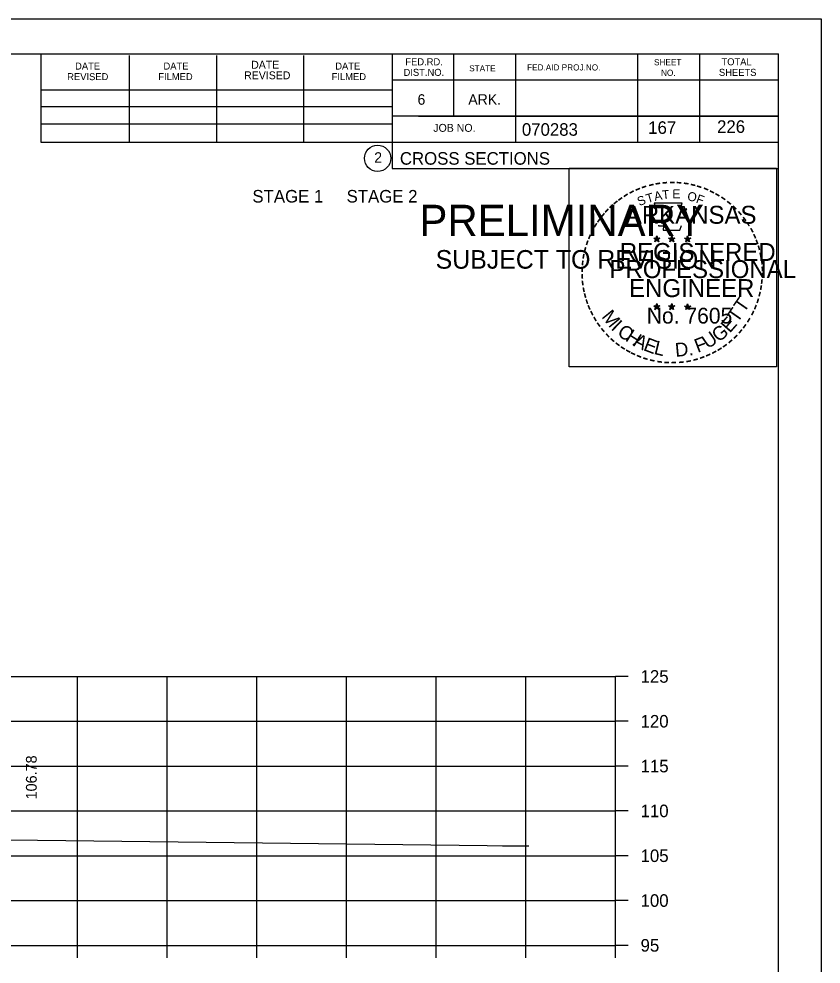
# Model space of a CAD drawing. Extents: x 1175611 to 1176402, y -433344 to -416213.
# Drawn here: x 1175854.4 to 1175943.9, y -428968.9 to -428863.4 of the extents above; entities that cross this region are included whole.
import ezdxf

# ---------------------------------------------------------------- set-up
doc = ezdxf.new("R2010")
doc.units = 0
for name, color, linetype in [('Default', 7, 'Continuous'), ('R_Axis', 7, 'Continuous'), ('R_Axis Annot', 7, 'Continuous'), ('R_Border', 7, 'Continuous'), ('R_Border Notes', 7, 'Continuous'), ('R_Border PE', 7, 'Continuous'), ('R_Border Prem', 7, 'Continuous'), ('R_Exist Surface', 7, 'Continuous'), ('R_Grid', 7, 'Continuous'), ('R_No Plot', 7, 'Continuous'), ('R_Xsect Elev', 7, 'Continuous')]:
    doc.layers.add(name, color=color, linetype=linetype)

msp = doc.modelspace()

# ---------------------------------------------------------------- linework, layer by layer
at = {"layer": 'R_Axis'}
for p, q in [((1175920.97, -428966.79), (1175920.97, -428936.79)), ((1175922.37, -428936.79), (1175920.97, -428936.79)), ((1175922.37, -428941.79), (1175920.97, -428941.79)), ((1175922.37, -428946.79), (1175920.97, -428946.79)), ((1175922.37, -428951.79), (1175920.97, -428951.79)), ((1175922.37, -428956.79), (1175920.97, -428956.79)), ((1175922.37, -428961.79), (1175920.97, -428961.79)), ((1175640.97, -428966.79), (1175920.97, -428966.79)), ((1175860.97, -428968.19), (1175860.97, -428966.79)), ((1175870.97, -428968.19), (1175870.97, -428966.79)), ((1175880.97, -428968.19), (1175880.97, -428966.79)), ((1175890.97, -428968.19), (1175890.97, -428966.79)), ((1175900.97, -428968.19), (1175900.97, -428966.79)), ((1175910.97, -428968.19), (1175910.97, -428966.79)), ((1175920.97, -428968.19), (1175920.97, -428966.79)), ((1175922.37, -428966.79), (1175920.97, -428966.79))]:
    msp.add_line(p, q, dxfattribs=at)
at = {"layer": 'R_Border'}
for p, q in [((1175622.97, -428867.33), (1175939.15, -428867.33)), ((1175856.89, -428877.21), (1175856.89, -428867.33)), ((1175866.75, -428877.21), (1175866.75, -428867.53)), ((1175876.51, -428877.21), (1175876.51, -428867.53)), ((1175886.19, -428877.21), (1175886.19, -428867.53)), ((1175896.05, -428867.33), (1175896.05, -428880.13)), ((1175902.89, -428867.33), (1175902.89, -428874.27)), ((1175909.83, -428867.33), (1175909.83, -428877.21)), ((1175923.41, -428867.33), (1175923.41, -428877.21)), ((1175930.35, -428867.33), (1175930.35, -428877.21)), ((1175939.15, -429072.79), (1175939.15, -428867.33)), ((1175939.15, -428870.27), (1175896.05, -428870.27)), ((1175939.15, -428870.25), (1175939.15, -428870.25)), ((1175856.89, -428871.35), (1175896.05, -428871.35)), ((1175856.89, -428873.21), (1175896.05, -428873.21)), ((1175939.15, -428874.27), (1175896.05, -428874.27)), ((1175899.01, -428874.27), (1175939.15, -428874.27)), ((1175856.89, -428877.21), (1175856.89, -428875.15)), ((1175856.89, -428875.15), (1175896.05, -428875.15)), ((1175939.15, -428877.21), (1175856.89, -428877.21)), ((1175896.05, -428880.13), (1175939.15, -428880.13))]:
    msp.add_line(p, q, dxfattribs=at)
msp.add_circle((1175894.44, -428878.99), 1.47, dxfattribs=at)
at = {"layer": 'R_Border PE'}
for p, q in [((1175925.23, -428887.88), (1175925.58, -428887.99)), ((1175925.23, -428887.88), (1175925.49, -428887.93)), ((1175925.23, -428887.88), (1175925.47, -428888.01)), ((1175925.37, -428888.29), (1175925.58, -428887.99)), ((1175925.37, -428888.29), (1175925.49, -428888.05)), ((1175925.58, -428887.63), (1175925.54, -428887.88)), ((1175925.58, -428887.99), (1175925.58, -428887.63)), ((1175925.58, -428887.63), (1175925.63, -428887.88)), ((1175925.93, -428887.88), (1175925.58, -428887.99)), ((1175925.8, -428888.29), (1175925.58, -428887.99)), ((1175925.93, -428887.88), (1175925.64, -428887.93)), ((1175925.8, -428888.29), (1175925.66, -428888)), ((1175925.93, -428887.88), (1175925.73, -428887.99)), ((1175926.9, -428887.88), (1175927.25, -428887.99)), ((1175926.9, -428887.88), (1175927.16, -428887.93)), ((1175926.9, -428887.88), (1175927.14, -428888.01)), ((1175927.04, -428888.29), (1175927.25, -428887.99)), ((1175927.04, -428888.29), (1175927.16, -428888.05)), ((1175927.25, -428887.63), (1175927.21, -428887.88)), ((1175927.25, -428887.99), (1175927.25, -428887.63)), ((1175927.25, -428887.63), (1175927.3, -428887.88)), ((1175927.6, -428887.88), (1175927.25, -428887.99)), ((1175927.47, -428888.29), (1175927.25, -428887.99)), ((1175927.6, -428887.88), (1175927.31, -428887.93)), ((1175927.47, -428888.29), (1175927.33, -428888)), ((1175927.6, -428887.88), (1175927.4, -428887.99)), ((1175928.67, -428887.9), (1175929.02, -428888.01)), ((1175928.67, -428887.9), (1175928.92, -428887.94)), ((1175928.67, -428887.9), (1175928.91, -428888.02)), ((1175928.8, -428888.3), (1175929.02, -428888.01)), ((1175928.8, -428888.3), (1175928.93, -428888.06)), ((1175929.02, -428887.64), (1175928.98, -428887.89)), ((1175929.02, -428888.01), (1175929.02, -428887.64)), ((1175929.02, -428887.64), (1175929.07, -428887.89)), ((1175929.36, -428887.9), (1175929.02, -428888.01)), ((1175929.23, -428888.3), (1175929.02, -428888.01)), ((1175929.36, -428887.9), (1175929.08, -428887.94)), ((1175929.23, -428888.3), (1175929.09, -428888.01)), ((1175929.36, -428887.9), (1175929.16, -428888)), ((1175925.37, -428888.29), (1175925.58, -428888.07)), ((1175925.8, -428888.29), (1175925.58, -428888.08)), ((1175927.04, -428888.29), (1175927.25, -428888.07)), ((1175927.47, -428888.29), (1175927.25, -428888.08)), ((1175928.8, -428888.3), (1175929.02, -428888.09)), ((1175929.23, -428888.3), (1175929.02, -428888.09)), ((1175925.58, -428895.2), (1175925.54, -428895.45)), ((1175925.58, -428895.57), (1175925.58, -428895.2)), ((1175925.58, -428895.2), (1175925.63, -428895.45)), ((1175927.25, -428895.2), (1175927.21, -428895.45)), ((1175927.25, -428895.57), (1175927.25, -428895.2)), ((1175927.25, -428895.2), (1175927.3, -428895.45)), ((1175929.02, -428895.21), (1175928.97, -428895.46)), ((1175929.02, -428895.58), (1175929.02, -428895.21)), ((1175929.02, -428895.21), (1175929.06, -428895.46)), ((1175925.23, -428895.46), (1175925.58, -428895.57)), ((1175925.23, -428895.46), (1175925.48, -428895.5)), ((1175925.23, -428895.46), (1175925.47, -428895.58)), ((1175925.36, -428895.86), (1175925.58, -428895.57)), ((1175925.36, -428895.86), (1175925.49, -428895.62)), ((1175925.36, -428895.86), (1175925.58, -428895.65)), ((1175925.93, -428895.46), (1175925.58, -428895.57)), ((1175925.79, -428895.86), (1175925.58, -428895.57)), ((1175925.79, -428895.86), (1175925.58, -428895.65)), ((1175925.93, -428895.46), (1175925.64, -428895.51)), ((1175925.79, -428895.86), (1175925.66, -428895.57)), ((1175925.93, -428895.46), (1175925.72, -428895.56)), ((1175926.9, -428895.46), (1175927.25, -428895.57)), ((1175926.9, -428895.46), (1175927.15, -428895.5)), ((1175926.9, -428895.46), (1175927.14, -428895.58)), ((1175927.03, -428895.86), (1175927.25, -428895.57)), ((1175927.03, -428895.86), (1175927.16, -428895.62)), ((1175927.03, -428895.86), (1175927.25, -428895.65)), ((1175927.6, -428895.46), (1175927.25, -428895.57)), ((1175927.46, -428895.86), (1175927.25, -428895.57)), ((1175927.46, -428895.86), (1175927.25, -428895.65)), ((1175927.6, -428895.46), (1175927.31, -428895.51)), ((1175927.46, -428895.86), (1175927.32, -428895.57)), ((1175927.6, -428895.46), (1175927.39, -428895.56)), ((1175928.67, -428895.47), (1175929.02, -428895.58)), ((1175928.67, -428895.47), (1175928.92, -428895.51)), ((1175928.67, -428895.47), (1175928.9, -428895.59)), ((1175928.8, -428895.87), (1175929.02, -428895.58)), ((1175928.8, -428895.87), (1175928.93, -428895.63)), ((1175928.8, -428895.87), (1175929.01, -428895.66)), ((1175929.23, -428895.87), (1175929.01, -428895.66)), ((1175929.36, -428895.47), (1175929.02, -428895.58)), ((1175929.23, -428895.87), (1175929.02, -428895.58)), ((1175929.36, -428895.47), (1175929.08, -428895.52)), ((1175929.23, -428895.87), (1175929.09, -428895.58)), ((1175929.36, -428895.47), (1175929.16, -428895.57))]:
    msp.add_line(p, q, dxfattribs=at)
for points in [[(1175925.28, -428884.01), (1175925.54, -428884.83)], [(1175928.79, -428884.93), (1175928.93, -428884.64), (1175928.24, -428884.67), (1175928.39, -428884.01), (1175925.28, -428884.01)], [(1175925.77, -428886.43), (1175925.77, -428886.52), (1175926.33, -428886.53), (1175926.28, -428887.01), (1175928.15, -428887.01), (1175928.35, -428886.47)], [(1175925.58, -428887.63), (1175925.8, -428888.29), (1175925.23, -428887.88), (1175925.93, -428887.88), (1175925.37, -428888.29), (1175925.58, -428887.63)], [(1175927.25, -428887.63), (1175927.47, -428888.29), (1175926.9, -428887.88), (1175927.6, -428887.88), (1175927.04, -428888.29), (1175927.25, -428887.63)], [(1175929.02, -428887.64), (1175929.23, -428888.3), (1175928.67, -428887.9), (1175929.36, -428887.9), (1175928.8, -428888.3), (1175929.02, -428887.64)], [(1175925.58, -428895.2), (1175925.79, -428895.86), (1175925.23, -428895.46), (1175925.93, -428895.46), (1175925.36, -428895.86), (1175925.58, -428895.2)], [(1175927.25, -428895.2), (1175927.46, -428895.86), (1175926.9, -428895.46), (1175927.6, -428895.46), (1175927.03, -428895.86), (1175927.25, -428895.2)], [(1175929.02, -428895.21), (1175929.23, -428895.87), (1175928.67, -428895.47), (1175929.36, -428895.47), (1175928.8, -428895.87), (1175929.02, -428895.21)]]:
    msp.add_lwpolyline(points, dxfattribs=at)
for centre, radius in [((1175925.58, -428888), 0.172), ((1175925.58, -428888), 0.145), ((1175925.58, -428888), 0.116), ((1175925.58, -428888), 0.0991), ((1175925.58, -428888), 0.0747), ((1175925.58, -428888), 0.0495), ((1175925.58, -428888), 0.0296), ((1175927.25, -428888), 0.172), ((1175927.25, -428888), 0.145), ((1175927.25, -428888), 0.116), ((1175927.25, -428888), 0.0991), ((1175927.25, -428888), 0.0747), ((1175927.25, -428888), 0.0495), ((1175927.25, -428888), 0.0296), ((1175929.02, -428888.01), 0.172), ((1175929.02, -428888.01), 0.145), ((1175929.02, -428888.01), 0.116), ((1175929.02, -428888.01), 0.0991), ((1175929.02, -428888.01), 0.0747), ((1175929.02, -428888.01), 0.0495), ((1175929.02, -428888.01), 0.0296), ((1175925.58, -428895.57), 0.172), ((1175925.58, -428895.57), 0.145), ((1175927.25, -428895.57), 0.172), ((1175927.25, -428895.57), 0.145), ((1175929.01, -428895.58), 0.172), ((1175929.01, -428895.58), 0.145), ((1175925.58, -428895.57), 0.116), ((1175925.58, -428895.57), 0.0991), ((1175925.58, -428895.57), 0.0747), ((1175925.58, -428895.57), 0.0495), ((1175925.58, -428895.57), 0.0296), ((1175927.25, -428895.57), 0.116), ((1175927.25, -428895.57), 0.0991), ((1175927.25, -428895.57), 0.0747), ((1175927.25, -428895.57), 0.0495), ((1175927.25, -428895.57), 0.0296), ((1175929.01, -428895.58), 0.116), ((1175929.01, -428895.58), 0.0991), ((1175929.01, -428895.58), 0.0747), ((1175929.01, -428895.58), 0.0495), ((1175929.01, -428895.58), 0.0296)]:
    msp.add_circle(centre, radius, dxfattribs=at)
at = {"layer": 'R_Exist Surface'}
msp.add_lwpolyline([(1175853.38, -428955.01), (1175906.65, -428955.66), (1175908.36, -428955.68), (1175911.27, -428955.68), (1175911.29, -428955.68)], dxfattribs=at)
at = {"layer": 'R_Grid'}
for p, q in [((1175640.97, -428936.79), (1175920.97, -428936.79)), ((1175860.97, -428966.79), (1175860.97, -428936.79)), ((1175870.97, -428966.79), (1175870.97, -428936.79)), ((1175880.97, -428966.79), (1175880.97, -428936.79)), ((1175890.97, -428966.79), (1175890.97, -428936.79)), ((1175900.97, -428966.79), (1175900.97, -428936.79)), ((1175910.97, -428966.79), (1175910.97, -428936.79)), ((1175920.97, -428966.79), (1175920.97, -428936.79)), ((1175640.97, -428941.79), (1175920.97, -428941.79)), ((1175640.97, -428946.79), (1175920.97, -428946.79)), ((1175640.97, -428951.79), (1175920.97, -428951.79)), ((1175640.97, -428956.79), (1175920.97, -428956.79)), ((1175640.97, -428961.79), (1175920.97, -428961.79)), ((1175640.97, -428966.79), (1175920.97, -428966.79))]:
    msp.add_line(p, q, dxfattribs=at)
at = {"layer": 'R_No Plot'}
msp.add_line((1175610.57, -428863.44), (1175943.91, -428863.44), dxfattribs=at)
for points in [[(1175610.57, -428863.44), (1175943.91, -428863.44), (1175943.91, -429076.77), (1175610.57, -429076.77)], [(1175915.82, -428880.1), (1175938.92, -428880.1), (1175938.92, -428902.25), (1175915.82, -428902.25)]]:
    msp.add_lwpolyline(points, close=True, dxfattribs=at)

# ---------------------------------------------------------------- texts
at = {"layer": 'Default'}
msp.add_text('STAGE 1     STAGE 2', height=1.4, dxfattribs=at).set_placement((1175880.47, -428883.92))
at = {"layer": 'R_Axis Annot'}
for s, p in [('125', (1175923.77, -428937.49)), ('120', (1175923.77, -428942.49)), ('115', (1175923.77, -428947.49)), ('110', (1175923.77, -428952.49)), ('105', (1175923.77, -428957.49)), ('100', (1175923.77, -428962.49)), ('95', (1175923.77, -428967.49))]:
    msp.add_text(s, height=1.4, dxfattribs=at).set_placement(p)
at = {"layer": 'R_Border'}
for s, height, p in [('FED.RD.', 0.782, (1175897.53, -428868.61)), ('SHEET', 0.684, (1175925.27, -428868.61)), ('TOTAL', 0.782, (1175932.79, -428868.61)), ('DATE', 0.782, (1175860.69, -428869.09)), ('DATE', 0.782, (1175870.55, -428869.09)), ('DATE', 0.879, (1175880.33, -428868.99)), ('DATE', 0.782, (1175889.71, -428869.09)), ('DIST.NO.', 0.782, (1175897.33, -428869.79)), ('STATE', 0.684, (1175904.65, -428869.29)), ('FED.AID PROJ.NO.', 0.684, (1175911.11, -428869.19)), ('SHEETS', 0.782, (1175932.51, -428869.79)), ('REVISED', 0.782, (1175859.81, -428870.27)), ('FILMED', 0.782, (1175869.97, -428870.27)), ('REVISED', 0.879, (1175879.55, -428870.17)), ('FILMED', 0.782, (1175889.31, -428870.27)), ('NO.', 0.684, (1175926.05, -428869.79)), ('6', 1.17, (1175898.89, -428873.01)), ('ARK.', 1.172, (1175904.55, -428873.01)), ('JOB NO.', 0.879, (1175900.65, -428876.03)), ('070283', 1.4, (1175910.53, -428876.47)), ('2', 1.17, (1175894.06, -428879.48)), ('CROSS SECTIONS', 1.4, (1175896.92, -428879.7))]:
    msp.add_text(s, height=height, rotation=360, dxfattribs=at).set_placement(p)
at = {"layer": 'R_Border Notes'}
for s, p in [('167', (1175924.62, -428876.26)), ('226', (1175932.3, -428876.15))]:
    msp.add_text(s, height=1.4, dxfattribs=at).set_placement(p)
at = {"layer": 'R_Border PE'}
for s, height, rotation, p in [('-', 1.6, 10.2193, (1175925.45, -428882.48)), ('-', 1.6, 5.8968, (1175926.18, -428882.37)), ('-', 1.6, 0.1862, (1175926.95, -428882.29)), ('-', 1.6, 357.743, (1175927.67, -428882.31)), ('-', 1.6, 352.1617, (1175928.42, -428882.36)), ('-', 1.6, 28.7918, (1175922.76, -428883.46)), ('-', 1.6, 24.3072, (1175923.39, -428883.15)), ('-', 1.6, 19.1761, (1175924.02, -428882.88)), ('-', 1.6, 13.6301, (1175924.77, -428882.64)), ('A', 1, 11.2132, (1175925.37, -428883.75)), ('T', 1, 6.0228, (1175926.22, -428883.58)), ('E', 1, 0.8323, (1175927.32, -428883.47)), ('O', 1, 350.4515, (1175928.93, -428883.68)), ('-', 1.6, 347.2049, (1175929.14, -428882.48)), ('-', 1.6, 342.3362, (1175929.77, -428882.63)), ('-', 1.6, 337.8551, (1175930.51, -428882.85)), ('-', 1.6, 334.1211, (1175931.14, -428883.13)), ('-', 1.6, 38.9507, (1175921.1, -428884.61)), ('-', 1.6, 36.2317, (1175921.58, -428884.23)), ('-', 1.6, 34.0636, (1175922.16, -428883.83)), ('S', 1, 21.594, (1175923.63, -428884.33)), ('T', 1, 16.4036, (1175924.54, -428884)), ('F', 1, 340.0707, (1175929.88, -428883.91)), ('-', 1.6, 329.6409, (1175931.72, -428883.41)), ('-', 1.6, 325.8627, (1175932.36, -428883.77)), ('-', 1.6, 320.5297, (1175932.97, -428884.2)), ('-', 1.6, 48.423, (1175920.22, -428885.5)), ('-', 1.6, 42.9622, (1175920.67, -428885.02)), ('ARKANSAS', 2, 360, (1175922.13, -428886.29)), ('-', 1.6, 315.5786, (1175933.57, -428884.68)), ('-', 1.6, 309.8797, (1175934.14, -428885.23)), ('-', 1.6, 54.2325, (1175919.41, -428886.56)), ('-', 1.6, 50.6142, (1175919.82, -428885.99)), ('-', 1.6, 306.6522, (1175934.66, -428885.84)), ('-', 1.6, 62.8713, (1175918.77, -428887.7)), ('-', 1.6, 58.0706, (1175919.08, -428887.08)), ('-', 1.4, 303.6753, (1175935.15, -428886.4)), ('-', 1.6, 299.6684, (1175935.47, -428887.01)), ('-', 1.6, 67.7743, (1175918.51, -428888.31)), ('DWB', 0.01, 360, (1175925.57, -428888)), ('DWB', 0.01, 360, (1175927.24, -428888)), ('DWB', 0.01, 360, (1175929, -428888.01)), ('-', 1.6, 294.6628, (1175935.79, -428887.62)), ('-', 1.6, 290.5728, (1175936.05, -428888.2)), ('-', 1.6, 75.461, (1175918.09, -428889.65)), ('-', 1.6, 72.3945, (1175918.29, -428888.94)), ('REGISTERED', 2, 360, (1175921.45, -428890.44)), ('-', 1.6, 285.1233, (1175936.28, -428888.78)), ('-', 1.6, 81.2013, (1175917.96, -428890.36)), ('-', 1.6, 280.5493, (1175936.48, -428889.52)), ('-', 1.6, 89.0622, (1175917.86, -428891.76)), ('-', 1.6, 85.1863, (1175917.89, -428891.06)), ('PROFESSIONAL', 2, 360, (1175920.3, -428892.35)), ('-', 1.6, 276.5962, (1175936.65, -428890.29)), ('-', 1.6, 274.3301, (1175936.71, -428891.01)), ('-', 1.6, 94.1959, (1175917.9, -428892.48)), ('-', 1.6, 269.9407, (1175936.74, -428891.64)), ('-', 1.6, 98.9479, (1175917.97, -428893.15)), ('ENGINEER', 2, 360, (1175922.49, -428894.47)), ('-', 1.6, 260.9953, (1175936.65, -428892.96)), ('-', 1.6, 263.5172, (1175936.72, -428892.31)), ('-', 1.6, 101.7149, (1175918.1, -428893.88)), ('-', 1.6, 105.4578, (1175918.27, -428894.48)), ('-', 1.6, 255.7626, (1175936.54, -428893.64)), ('-', 1.6, 109.0874, (1175918.48, -428895.11)), ('-', 1.6, 114.0643, (1175918.73, -428895.7)), ('T', 1.54, 55.055, (1175935.3, -428896.3)), ('-', 1.6, 247.8887, (1175936.14, -428895.03)), ('-', 1.6, 252.8681, (1175936.36, -428894.36)), ('-', 1.6, 115.7289, (1175919.04, -428896.32)), ('M', 1.54, 308.9175, (1175919.35, -428896.68)), ('No. 7605', 1.757, 360, (1175924.46, -428897.42)), ('DWB', 0.01, 360, (1175925.56, -428895.57)), ('DWB', 0.01, 360, (1175927.23, -428895.57)), ('DWB', 0.01, 360, (1175929, -428895.58)), ('T', 1.54, 55.055, (1175934.57, -428897.42)), ('-', 1.6, 244.6197, (1175935.87, -428895.66)), ('-', 1.6, 120.4471, (1175919.4, -428896.91)), ('-', 1.6, 125.8934, (1175919.8, -428897.47)), ('I', 1.54, 316.4636, (1175920.39, -428898)), ('E', 1.54, 48.7313, (1175933.72, -428898.55)), ('-', 1.6, 233.8452, (1175935.08, -428897.07)), ('-', 1.6, 239.0712, (1175935.48, -428896.42)), ('-', 1.6, 130.7181, (1175920.26, -428898.02)), ('-', 1.6, 134.2238, (1175920.78, -428898.57)), ('C', 1.54, 324.0197, (1175921.06, -428898.62)), ('H', 1.54, 327.5342, (1175921.97, -428899.28)), ('U', 1.54, 34.4052, (1175931.27, -428900.3)), ('G', 1.54, 38.2173, (1175932.47, -428899.57)), ('-', 1.6, 231.2538, (1175934.65, -428897.63)), ('-', 1.6, 138.9338, (1175921.3, -428899.03)), ('-', 1.6, 144.6463, (1175921.86, -428899.44)), ('A', 1.54, 332.5513, (1175922.83, -428899.81)), ('E', 1.54, 339.2068, (1175923.99, -428900.37)), ('L', 1.54, 346.2929, (1175925.18, -428900.8)), ('D.', 1.54, 5.2602, (1175927.68, -428901.14)), ('F', 1.54, 20.8202, (1175930.13, -428900.7)), ('-', 1.6, 221.0851, (1175933.65, -428898.71)), ('-', 1.6, 225.7653, (1175934.17, -428898.2)), ('-', 1.6, 148.0898, (1175922.42, -428899.81)), ('-', 1.6, 151.5704, (1175923, -428900.13)), ('-', 1.6, 154.6002, (1175923.52, -428900.38)), ('-', 1.6, 207.3568, (1175932.01, -428899.91)), ('-', 1.6, 212.2491, (1175932.56, -428899.57)), ('-', 1.6, 215.7363, (1175933.1, -428899.18)), ('-', 1.6, 158.5612, (1175924.15, -428900.63)), ('-', 1.6, 162.7983, (1175924.83, -428900.85)), ('-', 1.6, 167.5555, (1175925.55, -428901.01)), ('-', 1.6, 173.1155, (1175926.32, -428901.12)), ('-', 1.6, 176.5183, (1175927.07, -428901.17)), ('-', 1.6, 181.5918, (1175927.81, -428901.15)), ('-', 1.6, 185.8167, (1175928.62, -428901.08)), ('-', 1.6, 191.2858, (1175929.36, -428900.95)), ('-', 1.6, 195.4743, (1175930.09, -428900.75)), ('-', 1.6, 200.7184, (1175930.76, -428900.5)), ('-', 1.6, 204.2516, (1175931.38, -428900.23))]:
    msp.add_text(s, height=height, rotation=rotation, dxfattribs=at).set_placement(p)
at = {"layer": 'R_Border Prem'}
for s, height, p in [('PRELIMINARY', 3.5, (1175899.1, -428887.67)), ('DWB', 0.01, (1175899.85, -428885.82)), ('SUBJECT TO REVISION', 2.0751, (1175900.91, -428891.3))]:
    msp.add_text(s, height=height, rotation=360, dxfattribs=at).set_placement(p)
at = {"layer": 'R_Xsect Elev'}
msp.add_text('106.78', height=1.2, rotation=90, dxfattribs=at).set_placement((1175856.41, -428950.51))

doc.saveas('drawing.dxf')
